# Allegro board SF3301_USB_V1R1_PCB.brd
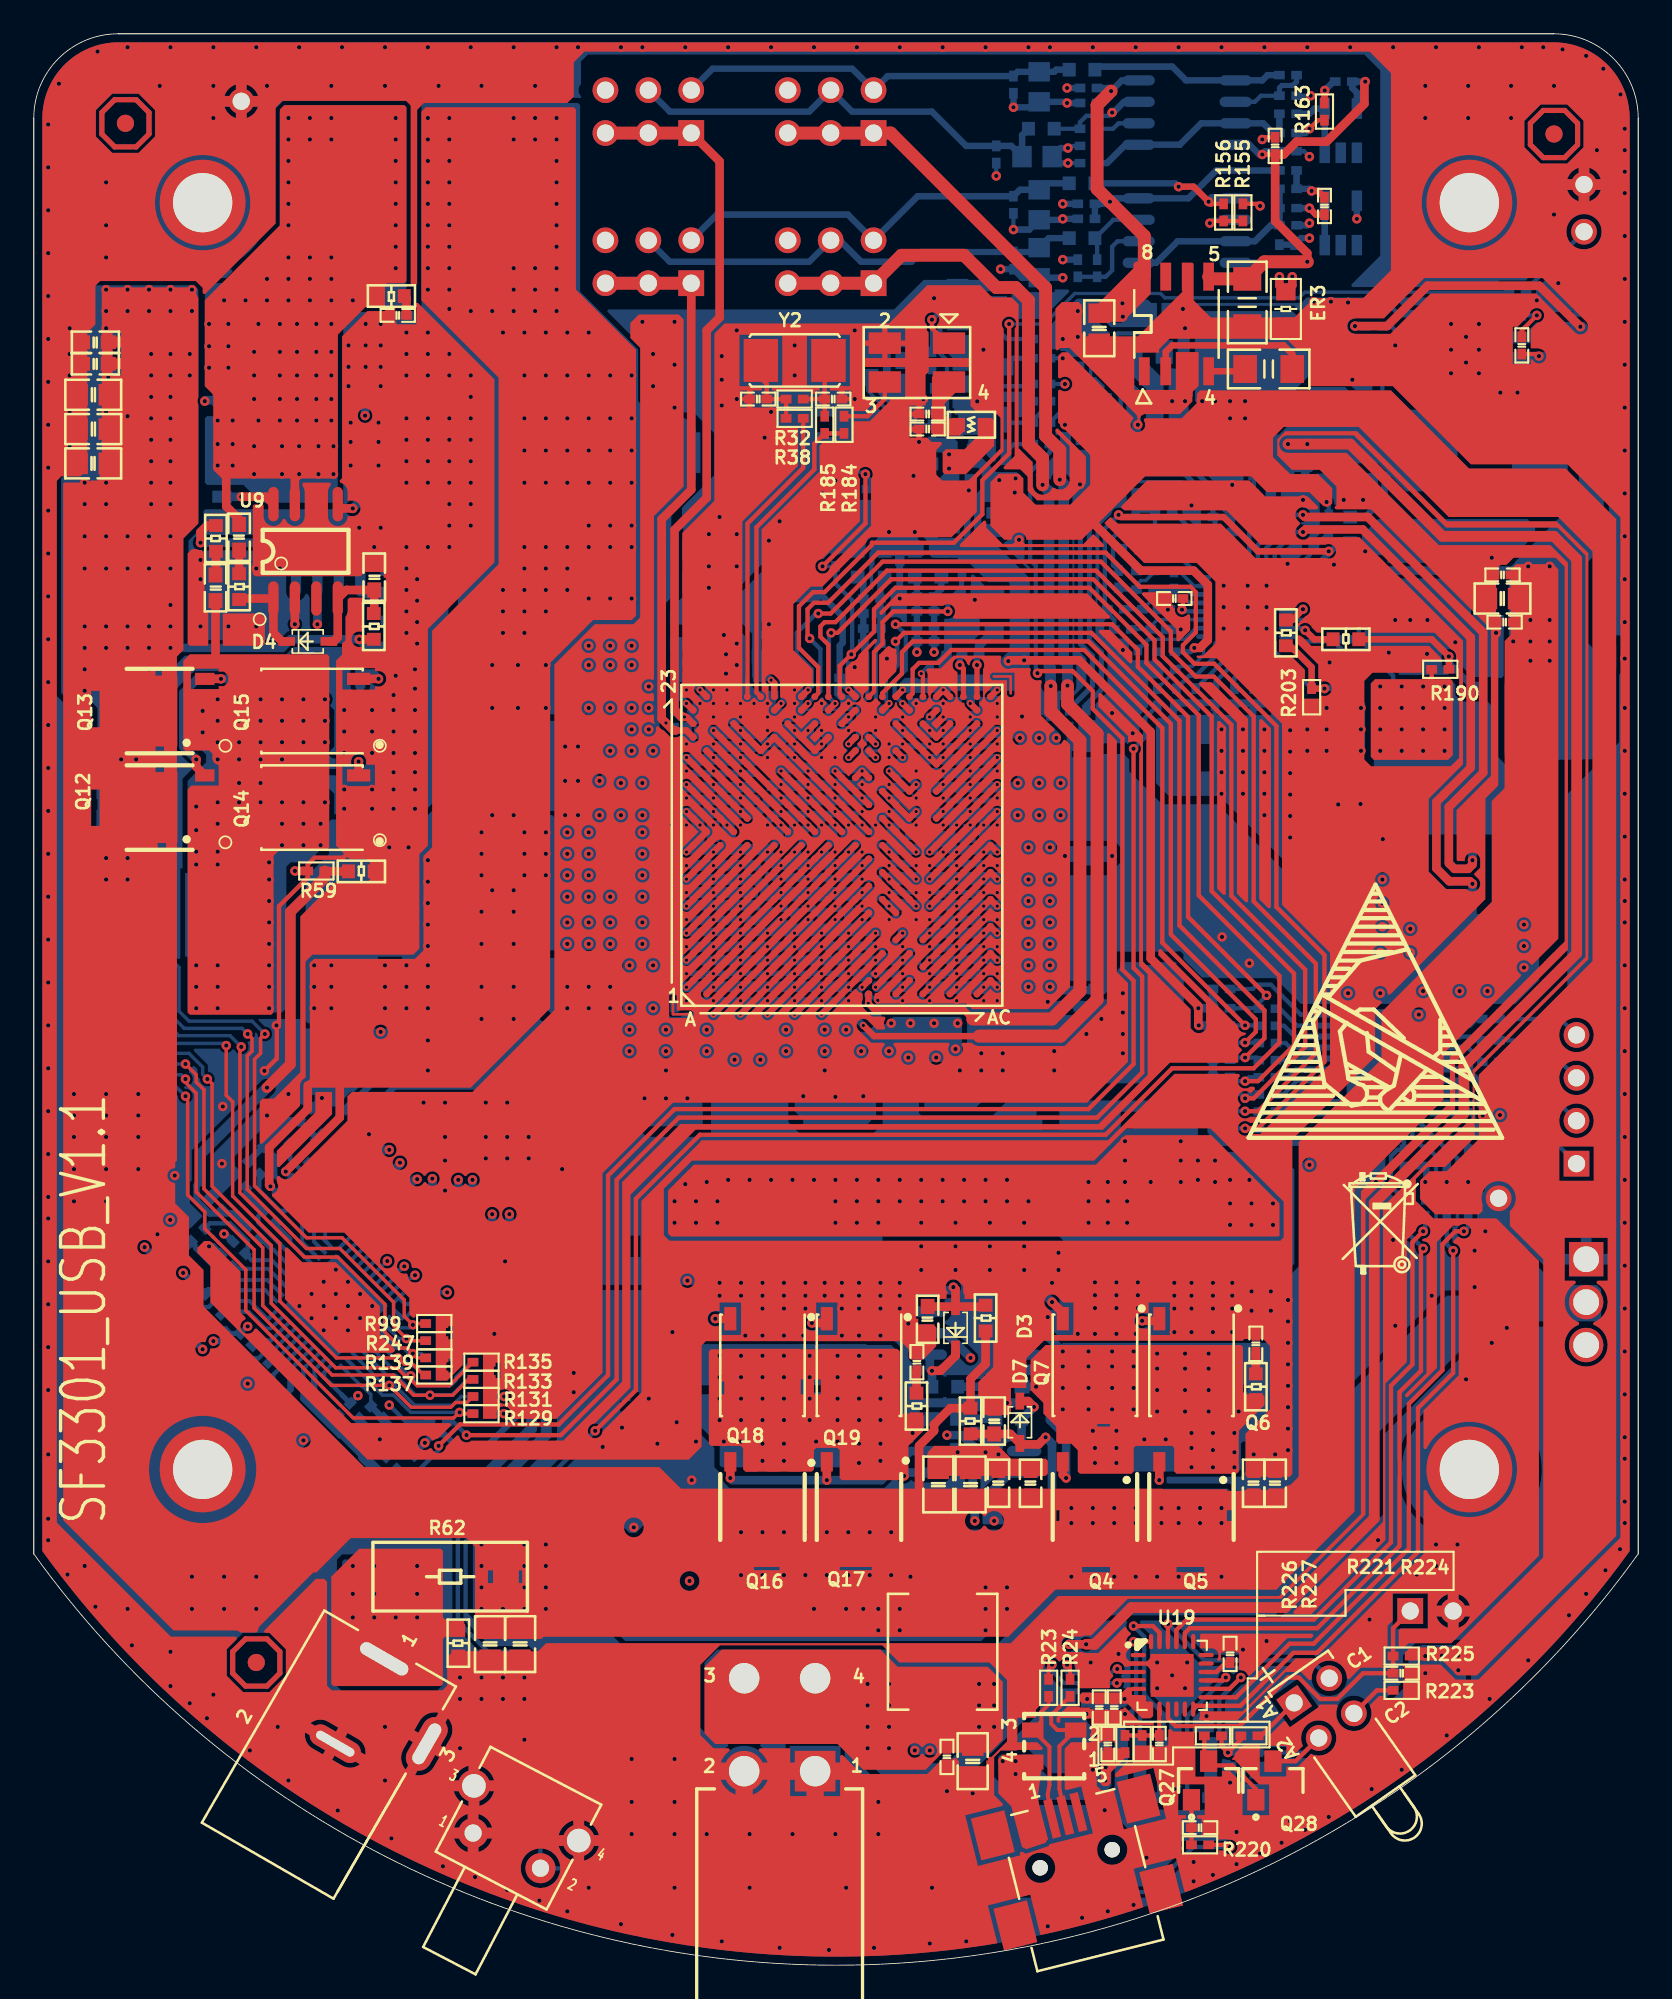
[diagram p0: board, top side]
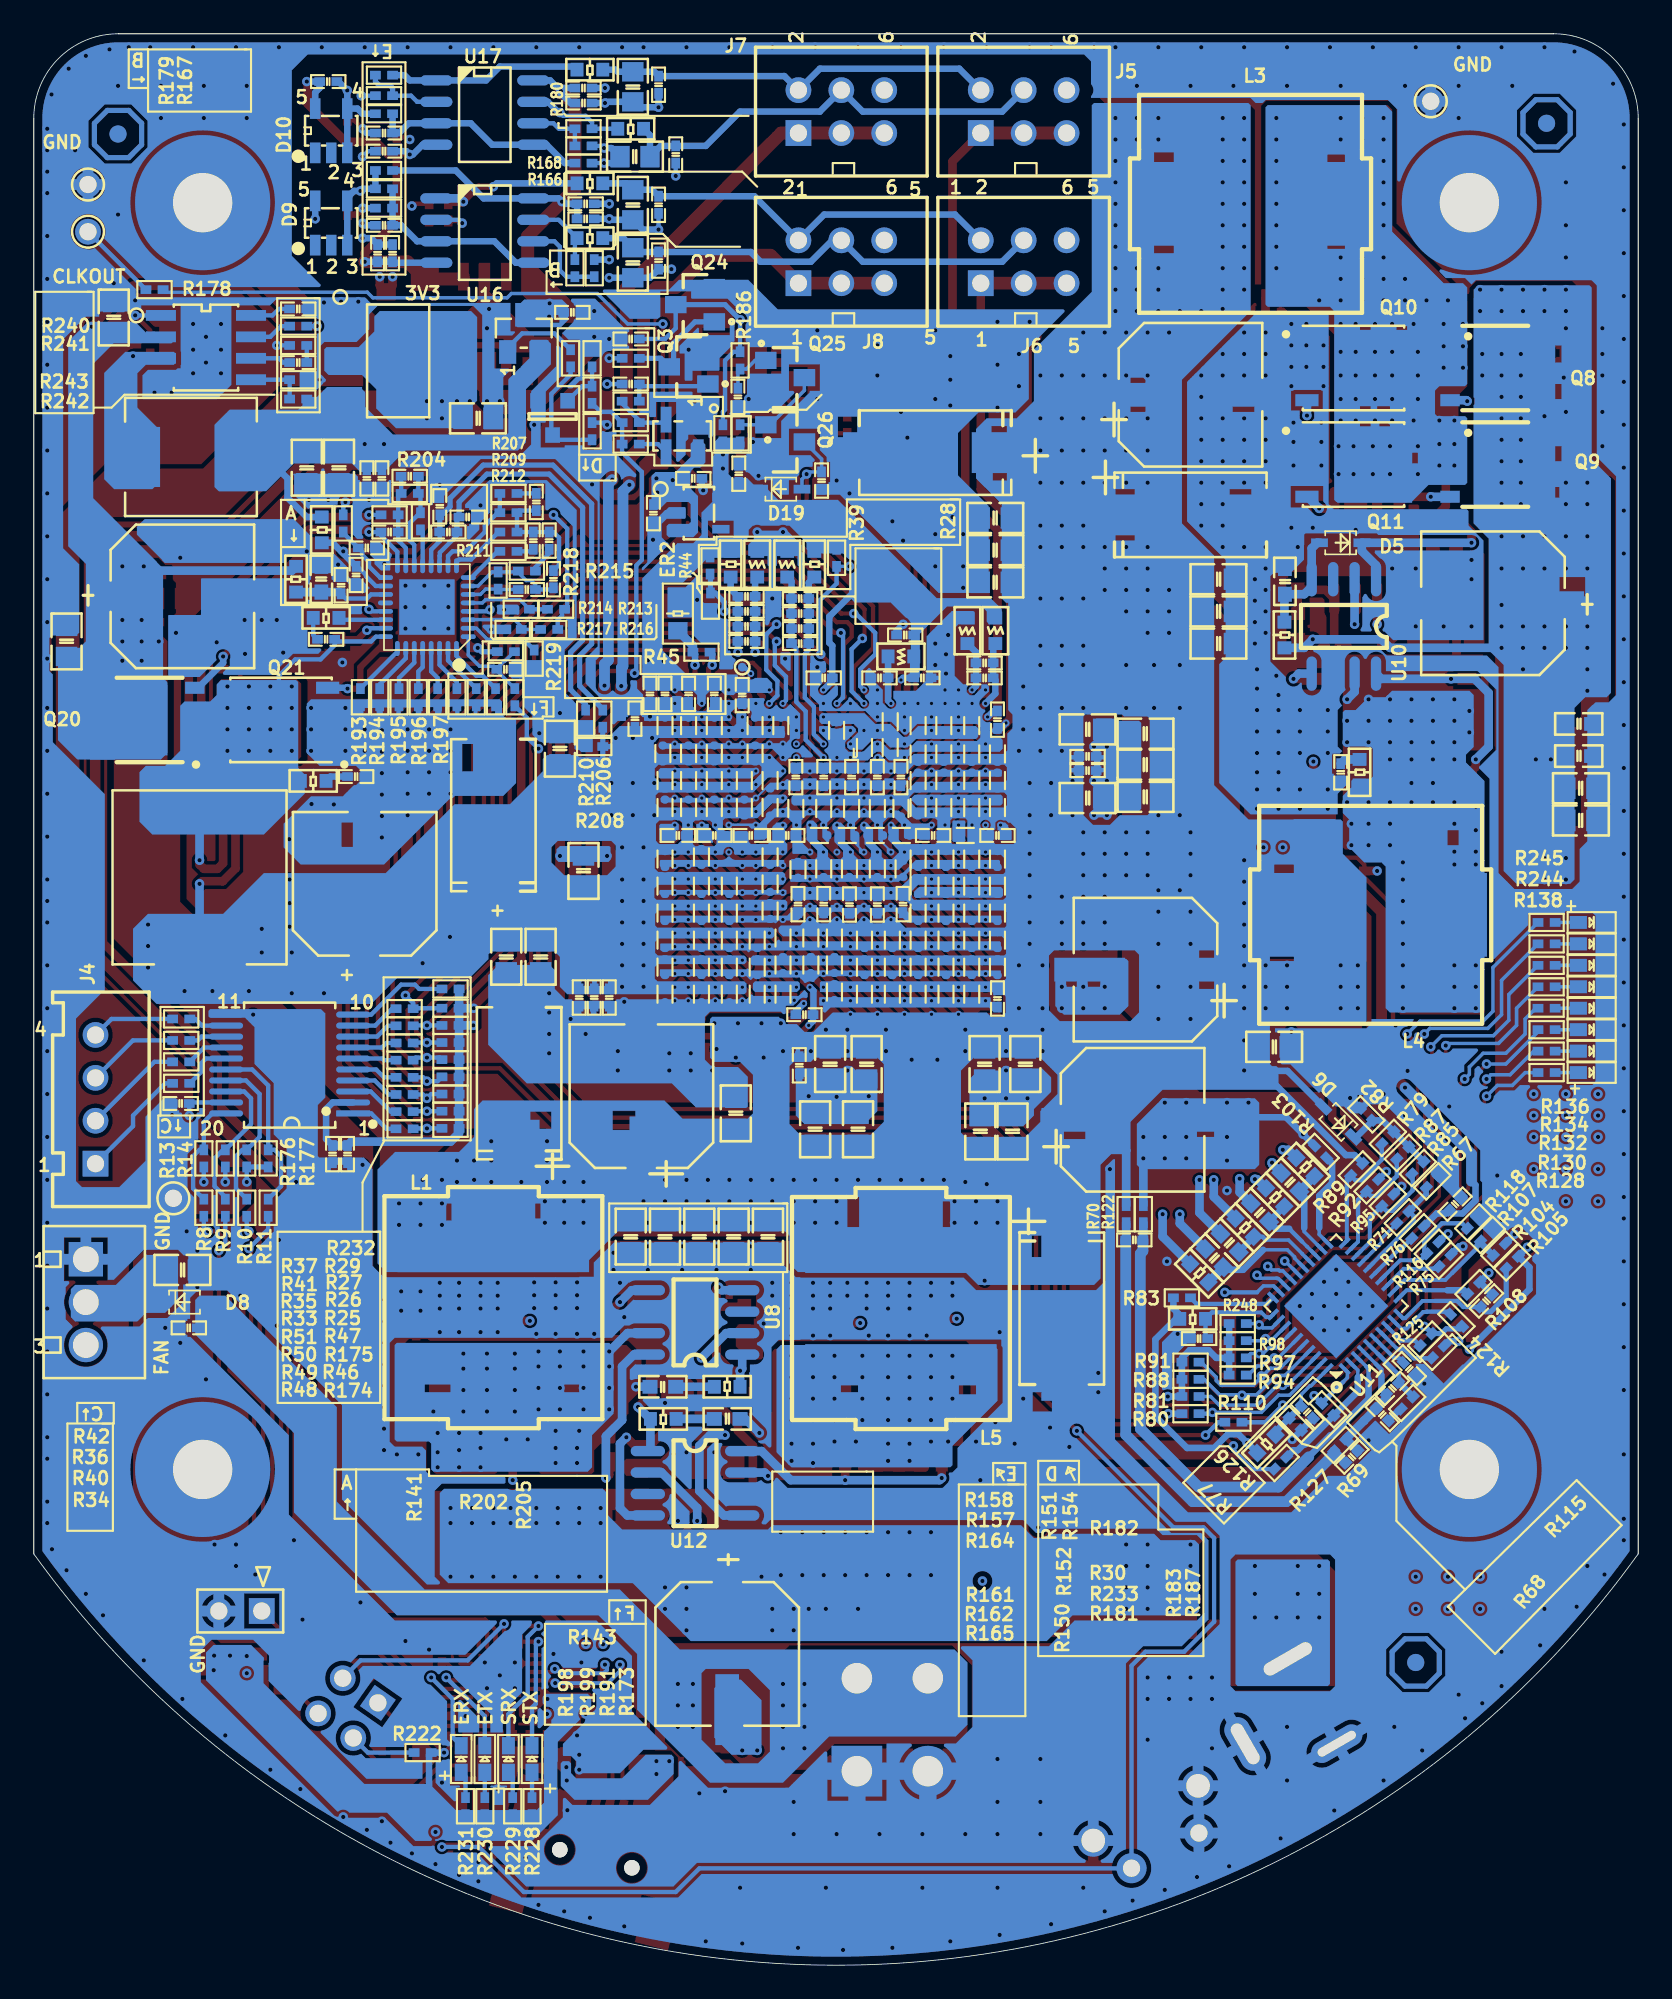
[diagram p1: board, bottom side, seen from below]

Outline 95 x 114.35 mm; copper layers: TOP, ART02, ART03, BOTTOM. Coordinates in mm from the lower left corner of the outline.
Outline path: 0,109.35 0,24.35 ; 0,109.35 arc(1.46,112.89) 5,114.35 ; 0,109.35 0,24.35 ; 0,24.35 arc(47.5,0) 95,24.35 ; 5,114.35 90,114.35 ; 5,114.35 90,114.35 ; 90,114.35 arc(93.53,112.89) 95,109.35 ; 95,109.35 95,24.35 ; 95,109.35 95,24.35

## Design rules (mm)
net group DIFF90: nets USB_DM USB_DP
net group DNRX0: nets DNRX0 N17535586
net group DNRX1: nets DNRX1 N17535592
net group DNTX0: nets DNTX0 N17535589
net group DNTX1: nets DNTX1 N17535595
net group ISP3: nets ISP3 RT8802A_PHASE3
net group ISP4: nets ISP4 RT8802A_PHASE4
net group LTC_PGD: nets LTC_PGD LTC_PGD_R
net group N16972391: nets N16972391 N16972492
net group N17253408: nets N17253408 N17254276
net group N17472254: nets N17472254 N17472271
net group N17472572: nets N17472572 N17488147
net group N17472645: nets N17472645 N17492409
net group N17535696: nets N17535696 N17535726
net group N17535699: nets N17535699 N17535729
net group N17535702: nets N17535702 N17535732
net group N17535705: nets N17535705 N17535735
net group RT8802A_PHASE1: nets N16973441 RT8802A_PHASE1
net group UART1_RX: nets UART1_RX UPTX0
net group UART1_TX: nets UART1_TX UPRX0
net group UART2_RX: nets UART2_RX UPTX1
net group UART2_TX: nets UART2_TX UPRX1
net group VCC_N0V5: nets N17032770 VCC_N0V5
net group VCC_P0V5: nets N17032029 VCC_P0V5
net group VID0: nets N16973189 VID0
net group VID1: nets N16973186 VID1
net group VID3: nets N16973195 VID3
net group VID4: nets N16973214 VID4
net group VID5: nets N16973217 VID5
net group 6314_ISEN: nets 6314_ISEN 6314_ISEN- N17472139 N17472149 N17472629 N17495070 N17497213
net group BTC_PGD: nets BTC_PGD N16975081 N17261273
net group FAN: nets 0 AVDD_THS BTC_GNDS_0 BTC_GNDS_1 BTC_VDD BTC_VDDS_0 BTC_VDDS_1 LTC_VDD N16884503 N16885409 N16885936 N16887961 N16887964 OSC_BP OSC_ZO RST_SF3301 VCC_1V8 VDDA_OSC VDDA_PLL0 VDDA_PLL1 VSSA_PLL0 VSSA_PLL1
net group ISN1: nets ISN1 ISN24 VCORE
net group N17472208: nets N17472208 N17472210 N17472223 N17472288
net group N17472302: nets N17472302 N17472317 N17489529
net group USB_DM: nets N17460832
net group USB_DP: nets N17460836
net group V6314_VCC: nets N17472408 N17472474 V6314_VCC VCC_5V0
net group VCC_1V0: nets N17031808 N17031818 VCC_1V0
net group VCC_N1V0: nets N17253373 N17253375 VCC_N1V0
net group VCC_P5V0: nets N17031806 N17031906 VCC_P5V0
net group XCLKIN: nets N16884499 N17511574 XCLKIN

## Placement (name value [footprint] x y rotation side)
C13  0.1uF  [C0402]  74.39 88.03 90 bottom
C14  10uF  [C0402]  75.28 88.03 270 bottom
C15  22uF  [C0805]  68.7 91.58 180 bottom
C18  27pF  [C0402]  47.34 92.73 0 top
C20  27pF  [C0402]  42.89 92.73 180 top
C22  0.1uF  [C0402]  86.3 51.02 180 bottom
C23  0.1uF  [C0402]  76.42 48.02 270 bottom
C24  0.1uF  [C0402]  38.7 76.22 0 bottom
C25  0.1uF  [C0402]  44.92 76.22 0 bottom
C26  4.7uF  [C0402]  58.51 75.27 270 bottom
C27  0.1uF  [C0402]  56.23 75.27 90 bottom
C28  0.1uF  [C0402]  53.05 75.2 90 bottom
C29  0.1uF  [C0402]  54.7 75.27 90 bottom
C30  0.1uF  [C0402]  57.62 75.27 90 bottom
C31  0.1uF  [C0402]  43.4 78.76 180 bottom
C32  0.1uF  [C0402]  48.22 76.22 180 bottom
C33  0.1uF  [C0402]  42.38 76.22 0 bottom
C34  2.2uF  [C0402]  49.62 78.25 0 bottom
C35  0.1uF  [C0402]  49.62 79.14 180 bottom
C36  0.01uF  [C0402]  49.62 80.03 180 bottom
C37  1000pF  [C0402]  49.62 80.91 180 bottom
C38  0.1uF  [C0402]  37.94 73.75 90 bottom
C39  0.1uF  [C0402]  49.37 56.28 180 bottom
C40  2.2uF  [C0402]  52.8 80.15 180 bottom
C41  0.1uF  [C0402]  52.8 78.37 0 bottom
C42  0.01uF  [C0402]  52.8 79.26 0 bottom
C43  1000pF  [C0402]  52.8 81.04 0 bottom
C44  4.7uF  [C0402]  58.31 85.97 270 bottom
C45  4.7uF  [C0402]  53.25 88.31 90 bottom
C46  22uF  [C0805]  38.7 53.36 270 bottom
C47  22uF  [C0805]  36.29 53.36 270 bottom
C48  22uF  [C0805]  45.68 53.36 270 bottom
C49  22uF  [C0805]  32.6 73.17 180 bottom
C50  22uF  [C0805]  47.84 53.36 270 bottom
C51  22uF  [C0805]  32.6 69.1 180 bottom
C62  10uF  [C0402]  43.53 62.82 270 bottom
C63  10uF  [C0402]  49.88 70.34 270 bottom
C64  10uF  [C0402]  48.22 70.34 270 bottom
C65  10uF  [C0402]  37.94 57.24 270 bottom
C66  10uF  [C0402]  46.57 70.34 270 bottom
C67  10uF  [C0402]  32.6 70.73 180 bottom
C68  10uF  [C0402]  49.75 62.82 270 bottom
C69  10uF  [C0402]  45.05 70.34 270 bottom
C70  10uF  [C0402]  43.65 70.34 270 bottom
C71  10uF  [C0402]  49.67 53.28 270 bottom
C72  10uF  [C0402]  46.7 62.8 270 bottom
C73  10uF  [C0402]  48.22 62.82 270 bottom
C74  10uF  [C0402]  41.75 66.89 0 bottom
C75  10uF  [C0402]  37.94 66.89 180 bottom
C76  10uF  [C0402]  32.6 71.57 180 bottom
C77  10uF  [C0402]  45.05 62.8 270 bottom
C78  2.2uF  [C0402_BGA]  37.94 63.89 270 bottom
C79  2.2uF  [C0402_BGA]  37.94 62.29 270 bottom
C80  2.2uF  [C0402_BGA]  37.94 60.69 270 bottom
C81  2.2uF  [C0402_BGA]  39.46 71.71 90 bottom
C82  2.2uF  [C0402_BGA]  41.11 70.14 90 bottom
C83  2.2uF  [C0402_BGA]  40.99 60.69 270 bottom
C84  2.2uF  [C0402_BGA]  37.94 70.14 90 bottom
C85  2.2uF  [C0402_BGA]  42.64 70.14 90 bottom
C86  2.2uF  [C0402_BGA]  44.16 59.09 270 bottom
C87  2.2uF  [C0402_BGA]  37.94 71.71 90 bottom
C88  2.2uF  [C0402_BGA]  52.16 59.09 270 bottom
C89  2.2uF  [C0402_BGA]  48.22 64.91 270 bottom
C90  2.2uF  [C0402_BGA]  37.94 59.09 270 bottom
C91  2.2uF  [C0402_BGA]  46.7 64.91 270 bottom
C92  2.2uF  [C0402_BGA]  37.94 65.49 270 bottom
C93  2.2uF  [C0402_BGA]  42.64 71.71 90 bottom
C94  2.2uF  [C0402_BGA]  49.88 68.49 270 bottom
C95  2.2uF  [C0402_BGA]  46.57 68.49 270 bottom
C96  2.2uF  [C0402_BGA]  44.29 73.62 90 bottom
C97  2.2uF  [C0402_BGA]  49.75 64.86 270 bottom
C98  2.2uF  [C0402_BGA]  40.99 65.49 270 bottom
C99  2.2uF  [C0402_BGA]  39.84 66.89 0 bottom
C100  2.2uF  [C0402_BGA]  47.46 73.11 270 bottom
C101  2.2uF  [C0402_BGA]  42.64 62.29 270 bottom
C102  2.2uF  [C0402_BGA]  45.81 72.09 270 bottom
C103  2.2uF  [C0402_BGA]  45.05 64.91 270 bottom
C104  2.2uF  [C0402_BGA]  39.46 65.49 270 bottom
C105  2.2uF  [C0402_BGA]  48.22 68.49 270 bottom
C106  2.2uF  [C0402_BGA]  43.53 64.91 270 bottom
C107  2.2uF  [C0402_BGA]  45.18 66.89 180 bottom
C108  2.2uF  [C0402_BGA]  48.99 60.82 270 bottom
C109  2.2uF  [C0402_BGA]  39.46 60.69 270 bottom
C110  2.2uF  [C0402_BGA]  42.64 60.69 270 bottom
C111  2.2uF  [C0402_BGA]  48.99 59.22 270 bottom
C112  2.2uF  [C0402_BGA]  48.48 66.89 180 bottom
C113  2.2uF  [C0402_BGA]  43.63 66.89 180 bottom
C114  2.2uF  [C0402_BGA]  39.46 59.09 270 bottom
C115  2.2uF  [C0402_BGA]  42.64 63.89 270 bottom
C116  2.2uF  [C0402_BGA]  46.83 66.89 180 bottom
C117  2.2uF  [C0402_BGA]  44.16 57.49 270 bottom
C118  2.2uF  [C0402_BGA]  52.16 57.49 270 bottom
C119  2.2uF  [C0402_BGA]  50.64 59.22 270 bottom
C120  2.2uF  [C0402_BGA]  50.64 57.49 270 bottom
C121  2.2uF  [C0402_BGA]  44.16 60.69 270 bottom
C122  2.2uF  [C0402_BGA]  45.81 59.09 270 bottom
C123  2.2uF  [C0402_BGA]  41.11 71.71 90 bottom
C124  2.2uF  [C0402_BGA]  50.64 60.82 270 bottom
C125  2.2uF  [C0402_BGA]  45.81 57.49 270 bottom
C126  2.2uF  [C0402_BGA]  41.11 73.39 90 bottom
C127  2.2uF  [C0402_BGA]  42.64 73.39 90 bottom
C128  2.2uF  [C0402_BGA]  40.99 62.29 270 bottom
C129  2.2uF  [C0402_BGA]  40.99 63.89 270 bottom
C130  2.2uF  [C0402_BGA]  41.11 68.54 90 bottom
C131  2.2uF  [C0402_BGA]  42.64 65.49 270 bottom
C132  2.2uF  [C0402_BGA]  39.46 57.49 270 bottom
C133  2.2uF  [C0402_BGA]  47.59 57.62 270 bottom
C134  2.2uF  [C0402_BGA]  47.59 60.82 270 bottom
C135  2.2uF  [C0402_BGA]  39.46 70.14 90 bottom
C136  2.2uF  [C0402_BGA]  43.65 68.49 270 bottom
C137  2.2uF  [C0402_BGA]  44.29 72.09 270 bottom
C138  2.2uF  [C0402_BGA]  39.46 68.54 90 bottom
C139  2.2uF  [C0402_BGA]  45.81 60.69 270 bottom
C140  2.2uF  [C0402_BGA]  42.64 57.49 270 bottom
C141  2.2uF  [C0402_BGA]  40.99 57.49 270 bottom
C142  2.2uF  [C0402_BGA]  39.46 63.89 270 bottom
C143  2.2uF  [C0402_BGA]  39.46 73.39 90 bottom
C144  2.2uF  [C0402_BGA]  42.64 68.54 90 bottom
C145  2.2uF  [C0402_BGA]  37.94 68.54 90 bottom
C146  2.2uF  [C0402_BGA]  45.05 68.49 270 bottom
C147  2.2uF  [C0402_BGA]  42.64 59.09 270 bottom
C148  2.2uF  [C0402_BGA]  47.59 59.22 270 bottom
C149  2.2uF  [C0402_BGA]  40.99 59.09 270 bottom
C150  2.2uF  [C0402_BGA]  39.46 62.29 270 bottom
C201  22uF  [C0805]  62.45 64.79 90 bottom
C202  22uF  [C0805]  64.99 59.71 270 bottom
C203  22uF  [C0805]  67.02 59.71 270 bottom
C204  22uF  [C0805]  63.85 72.02 90 bottom
C205  10uF  [C0402]  50.38 66.89 180 bottom
C206  10uF  [C0402]  52.54 66.89 180 bottom
C207  10uF  [C0402]  56.86 66.89 0 bottom
C208  10uF  [C0402]  54.7 66.89 0 bottom
C209  2.2uF  [C0402_BGA]  56.23 71.74 90 bottom
C210  2.2uF  [C0402_BGA]  50.76 73.39 90 bottom
C211  2.2uF  [C0402_BGA]  53.81 59.09 270 bottom
C212  2.2uF  [C0402_BGA]  53.81 57.49 270 bottom
C213  2.2uF  [C0402_BGA]  56.23 70.14 90 bottom
C214  2.2uF  [C0402_BGA]  55.46 65.62 270 bottom
C215  2.2uF  [C0402_BGA]  57.62 68.54 90 bottom
C216  2.2uF  [C0402_BGA]  54.7 70.14 90 bottom
C217  2.2uF  [C0402_BGA]  51.4 64.02 270 bottom
C218  2.2uF  [C0402_BGA]  52.29 73.39 90 bottom
C219  2.2uF  [C0402_BGA]  57.62 70.14 90 bottom
C220  2.2uF  [C0402_BGA]  51.4 68.54 270 bottom
C221  2.2uF  [C0402_BGA]  51.4 70.14 270 bottom
C222  2.2uF  [C0402_BGA]  52.92 70.14 90 bottom
C223  2.2uF  [C0402_BGA]  52.92 68.54 90 bottom
C224  2.2uF  [C0402_BGA]  54.7 73.39 90 bottom
C225  2.2uF  [C0402_BGA]  54.7 71.74 90 bottom
C226  2.2uF  [C0402_BGA]  53.81 60.69 270 bottom
C227  2.2uF  [C0402_BGA]  51.4 62.42 270 bottom
C228  2.2uF  [C0402_BGA]  54.7 68.54 90 bottom
C229  2.2uF  [C0402_BGA]  56.23 73.39 90 bottom
C230  2.2uF  [C0402_BGA]  52.29 71.74 90 bottom
C231  2.2uF  [C0402_BGA]  55.46 63.89 270 bottom
C232  2.2uF  [C0402_BGA]  56.23 68.54 90 bottom
C233  2.2uF  [C0402_BGA]  51.4 65.62 270 bottom
C234  2.2uF  [C0402_BGA]  57.62 73.39 90 bottom
C235  2.2uF  [C0402_BGA]  52.16 60.69 270 bottom
C236  2.2uF  [C0402_BGA]  53.81 63.89 270 bottom
C237  2.2uF  [C0402_BGA]  55.46 60.69 270 bottom
C238  2.2uF  [C0402_BGA]  57.62 65.49 270 bottom
C239  2.2uF  [C0402_BGA]  57.62 63.89 270 bottom
C240  2.2uF  [C0402_BGA]  57.62 62.29 270 bottom
C241  2.2uF  [C0402_BGA]  57.62 57.49 270 bottom
C242  2.2uF  [C0402_BGA]  55.46 62.29 270 bottom
C243  2.2uF  [C0402_BGA]  53.81 62.29 270 bottom
C244  2.2uF  [C0402_BGA]  57.62 60.69 270 bottom
C245  2.2uF  [C0402_BGA]  57.62 59.09 270 bottom
C246  2.2uF  [C0402_BGA]  55.46 59.09 270 bottom
C247  2.2uF  [C0402_BGA]  55.46 57.49 270 bottom
C248  2.2uF  [C0402_BGA]  57.75 71.74 90 bottom
C249  10uF/16V  [C0805]  28.79 19.01 90 top
C250  0.1uF/16V  [C0603]  72.23 28.53 270 top
C251  0.1uF/16V  [C0603]  57.75 34.25 180 bottom
C252  10uF/16V  [C0805]  27.02 19.01 90 top
C253  0.1uF/16V  [C0603]  73.5 28.53 270 top
C254  0.1uF/16V  [C0603]  52.92 38.24 270 top
C255  1000pF  [C0402]  54.07 12.33 270 top
C256  10uF/16V  [C0805]  55.59 12.08 270 top
C257  10uF/16V  [C0805]  3.52 88.92 180 top
C258  3.3nF  [C0402]  72.35 36.79 270 top
C259  0.1uF/16V  [C0603]  12.16 84.54 270 top
C260  10uF/16V  [C0805]  3.39 67.78 0 bottom
C261  0.1uF/16V  [C0603]  3.52 71.59 0 bottom
C262  10uF/16V  [C0805]  3.39 69.68 0 bottom
C263  0.1uF/16V  [C0603]  3.52 73.49 0 bottom
C264  0.1uF/16V  [C0603]  20.16 82.18 90 top
C265  68nF  [C0402]  13.55 35.32 225 bottom
C267  47pF  [C0402]  14.54 34.15 135 bottom
C268  2.2nF  [C0402]  15.16 32.6 225 bottom
C269  1.5nF  [C0402]  16.95 30.08 135 bottom
C270  3.3nF  [C0402]  21.55 97.68 0 top
C271  0.1uF  [C0402]  29.84 42.94 0 bottom
C272  10uF/16V  [C0805]  3.52 90.95 0 top
C273  0.1uF/16V  [C0603]  3.65 94.81 0 top
C274  10uF/16V  [C0805]  3.52 92.98 0 top
C275  0.1uF/16V  [C0603]  3.65 96.08 0 top
C276  270pF/NC  [C0402]  10.84 45.06 315 bottom
C277  0.1uF/16V  [C0603]  10.76 81.55 90 top
C278  0.1uF/16V  [C0603]  20.92 81.93 90 bottom
C279  0.1uF/NC  [C0402]  19.59 32.75 45 bottom
C280  1uF/16V  [C0603]  20.6 46.36 225 bottom
C281  3.3nF  [C0402]  17.62 70.63 90 bottom
C282  1uF/16V  [C0603]  22.4 44.56 225 bottom
C283  1uF/16V  [C0603]  24.19 42.77 225 bottom
C284  1uF/16V  [C0603]  25.09 41.87 225 bottom
C285  0.1uF/16V  [C0603]  59.02 28.53 270 top
C286  0.1uF/16V  [C0603]  53.94 32.34 0 bottom
C287  2.2uF  [C0402]  26 37.1 0 bottom
C288  10uF/16V  [C0805]  55.46 28.46 270 top
C289  0.1uF/16V  [C0603]  57.11 28.53 270 top
C290  10uF/16V  [C0805]  53.56 28.46 270 top
C291  0.1uF/16V  [C0603]  56.86 32.22 90 top
C292  0.1uF/NC  [C0402]  8.98 39.33 315 bottom
C294  3.3nF  [C0402]  52.29 35.7 270 top
C297  22uF  [C0805]  29.17 69.17 0 bottom
C298  22uF  [C0805]  24.86 82.06 180 bottom
C299  22uF  [C0805]  29.17 71.08 0 bottom
C300  22uF  [C0805]  57.62 43.14 270 bottom
C301  22uF  [C0805]  53.56 43.14 270 bottom
C302  22uF  [C0805]  55.59 43.14 270 bottom
C303  22uF  [C0805]  51.53 43.14 270 bottom
C304  22uF  [C0805]  21.55 54.37 180 bottom
C305  22uF  [C0805]  53.43 50.43 90 bottom
C306  22uF  [C0805]  59.65 43.14 270 bottom
C307  22uF  [C0805]  29.17 72.91 0 bottom
C308  22uF  [C0805]  24.86 78.25 180 bottom
C309  22uF  [C0805]  48.73 49.49 90 bottom
C310  22uF  [C0805]  46.19 49.49 90 bottom
C311  22uF  [C0805]  38.95 49.36 90 bottom
C312  22uF  [C0805]  37.05 49.36 90 bottom
C313  22uF  [C0805]  38.06 83.78 0 bottom
C314  22uF  [C0805]  38.06 85.68 0 bottom
C315  22uF  [C0805]  38.06 81.87 0 bottom
C316  22uF  [C0805]  24.86 80.15 180 bottom
C318  10uF/16V  [C0805]  86.96 80.91 180 top
C319  0.1uF  [C0402]  87.09 79.52 180 top
C320  10uF/16V  [C0805]  93.06 78.37 90 bottom
C321  0.01uF  [C0402]  86.96 82.31 0 top
C323  10uF  [C0402]  61.81 57.29 270 bottom
C324  10uF  [C0402]  62.7 57.29 270 bottom
C325  10uF  [C0402]  60.92 57.29 270 bottom
C326  0.1uF  [C0402]  85.82 37.73 0 bottom
C327  10uF/16V  [C0805]  86.2 41.16 180 bottom
C328  0.1uF  [C0402]  63.11 97.86 180 bottom
C329  22uF  [C0805]  63.08 96.92 270 top
C330  22uF  [C0805]  78.83 88.66 270 bottom
C331  10uF/16V  [C0805]  90.26 97.55 90 bottom
C332  100uF  [C1206]  73.12 94.5 180 top
C333  100uF  [C1206]  71.85 98.44 270 top
C334  0.1uF  [C0402]  62.32 104.28 0 bottom
C335  0.1uF  [C0402]  62.45 111.14 0 bottom
C336  22uF  [C0805]  59.53 104.23 270 bottom
C337  0.1uF  [C0402]  58 104.23 270 bottom
C338  0.1uF  [C0402]  74.26 103.01 0 bottom
C339  0.1uF  [C0402]  74.64 101.36 270 bottom
C340  0.1uF  [C0402]  74.26 108.47 0 bottom
C341  0.1uF  [C0402]  74.26 107.4 180 bottom
C342  22uF  [C0805]  59.53 111.21 270 bottom
C343  0.1uF  [C0402]  58 111.34 270 bottom
C344  4.7uF  [C0402]  76.42 104.16 270 top
C345  4.7uF  [C0402]  77.56 111.52 0 bottom
C346  22uF  [C0805]  59.53 100.8 270 bottom
C347  0.1uF  [C0402]  58 100.92 270 bottom
C348  22uF  [C0805]  59.4 107.08 0 bottom
C349  0.1uF  [C0402]  56.99 107.2 270 bottom
C350  0.1uF  [C0402]  55.95 88.03 180 bottom
C351  2.2uF  [C0402]  52.92 91.84 180 top
C352  0.1uF  [C0402]  52.92 90.95 180 top
C353  0.1uF  [C0402]  59.65 93.61 180 bottom
C354  0.1uF  [C0402]  59.65 96.28 180 bottom
C355  0.1uF  [C0402]  53.3 92.85 90 bottom
C356  0.1uF  [C0402]  48.35 87.9 90 bottom
C357  0.1uF  [C0402]  75.91 82.31 90 bottom
C358  4.7uF/16V  [C0603]  77.97 82.06 270 bottom
C359  0.1uF  [C0402]  67.07 76.72 180 bottom
C360  1uF  [C0402]  75.28 83.91 180 bottom
C361  0.1uF  [C0402]  77.69 78.5 180 bottom
C362  0.1uF  [C0402]  73.93 84.85 0 bottom
C363  1nF  [C0402]  75.91 70.37 0 bottom
C364  0.01uF  [C0402]  72.74 88.15 0 bottom
C365  0.1uF  [C0402]  59.4 73.8 270 bottom
C366  10pF/NC  [C0402]  70.96 86.38 90 bottom
C367  3.3nF  [C0402]  65.24 86.63 270 bottom
C368  10pF/NC  [C0402]  70.45 84.85 0 bottom
C369  1nF  [C0402]  65.42 84.34 90 bottom
C370  10pF/NC  [C0402]  69.31 85.74 0 bottom
C371  100pF  [C0402]  64.23 82.06 90 bottom
C372  0.01uF  [C0402]  67.53 80.91 0 top
C373  1nF  [C0402]  65.8 81.45 180 bottom
C374  6.8nF  [C0402]  64.48 84.34 90 bottom
C375  0.1uF  [C0402]  69.05 8.14 180 top
C376  4.7uF  [C0402]  63.97 15.26 90 top
C377  0.1uF  [C0402]  63.08 15.26 90 top
C378  4.7uF/NC  [C0402]  70.83 18.43 270 top
C379  0.1uF  [C0402]  80.99 17.29 180 top
C380  10uF  [C0402]  63.59 13.1 270 top
C381  2.2uF/NC  [C0402]  66.64 13.1 90 top
C382  2.2uF  [C0402]  38.7 77.1 0 bottom
C383  4.7uF  [C0402]  62.32 103.39 0 bottom
C384  4.7uF  [C0402]  73.75 101.36 270 bottom
C385  4.7uF  [C0402]  62.45 110.25 0 bottom
C386  4.7uF  [C0402]  73.5 107.71 270 top
C387  22uF  [C0805]  76.93 88.66 270 bottom
C388  0.1uF  [C0402]  88.1 95.9 270 top
C389  3.3nF  [C0402]  79.34 94.88 180 bottom
C390  0.01uF  [C0402]  79.34 98.06 0 bottom
C391  0.1uF  [C0402]  76.8 81.7 270 bottom
C392  4.7uF  [C0402]  77.31 48.02 270 bottom
CP1  270uF/16V  [CAP_D8_SMT]  53.94 18.43 270 bottom
CP2  270uF/16V  [CAP_D8_SMT]  8.6 80.64 0 bottom
CP3  1000uF/2.5V  [CAP_D8_SMT]  26.51 92.98 180 bottom
CP4  1000uF/2.5V  [CAP_D8_SMT]  59.02 51.45 90 bottom
CP5  1000uF/2.5V  [CAP_D8_SMT]  29.17 58.94 0 bottom
CP6  1000uF/2.5V  [CAP_D8_SMT]  29.94 50.05 180 bottom
CP7  1000uF/2.5V  [CAP_D8_SMT]  75.4 64.02 90 bottom
CP8  270uF/16V  [CAP_D8_SMT]  86.2 81.04 180 bottom
D1  LED ARRAY  [A694B]  77.12 14.18 125 top
D2  SP0503BAHTG  [SOT143-4]  60.42 12.97 90 top
D3  1N4148  [SOD323]  54.57 37.73 270 top
D4  1N4148  [SOD323]  16.22 78.37 180 top
D5  1N4148  [SOD323]  17.62 84.22 180 bottom
D6  1N4148  [SOD323]  17.74 49.93 225 bottom
D7  1N4148  [SOD323]  58.38 32.15 90 top
D8  1N4148  [SOD323]  86.07 39.26 0 bottom
D9  TL431CDBV  [SOT-23-5]  77.39 103.15 180 bottom
D10  TL431CDBV  [SOT-23-5]  77.39 108.61 180 bottom
D13  GREEN  [LED0603]  2.76 52.85 180 bottom
D14  GREEN  [LED0603]  2.76 54.12 180 bottom
D15  GREEN  [LED0603]  2.76 55.39 180 bottom
D16  GREEN  [LED0603]  2.76 56.66 180 bottom
D17  GREEN  [LED0603]  2.76 57.93 180 bottom
D18  GREEN  [LED0603]  2.76 59.2 180 bottom
D19  1N4148  [SOD323]  50.76 87.39 0 bottom
D20  GREEN  [LED0603]  65.5 12.21 90 bottom
D21  GREEN  [LED0603]  66.89 12.21 90 bottom
D22  GREEN  [LED0603]  68.29 12.21 90 bottom
D23  GREEN  [LED0603]  69.69 12.21 90 bottom
D24  GREEN  [LED0603]  2.76 60.47 180 bottom
D25  GREEN  [LED0603]  2.76 61.74 180 bottom
ER2  ETCH_RES  [R0805]  56.86 80.03 90 bottom
ER3  ETCH_RES  [R0805]  74.13 98.06 270 top
FB4  BEAD  [FB0603]  38.06 79.01 270 bottom
FB5  BEAD  [FB0603]  43.65 77.49 0 bottom
FB7  BEAD  [FB0603]  50.38 82.95 90 bottom
FB9  BEAD  [FB0603]  52.16 82.95 90 bottom
FB10  BEAD  [FB0603]  55.51 91.2 0 top
FB11  BEAD  [FB0603]  39.72 79.01 90 bottom
H1  HOLE  [HOLE3_5P-8MM]  85 104.35 0 top
H2  HOLE  [HOLE3_5P-8MM]  10 29.35 0 top
H3  HOLE  [HOLE3_5P-8MM]  10 104.35 0 top
H4  HOLE  [HOLE3_5P-8MM]  85 29.35 0 top
J2  HDR2/NC  [HDR2_2_54MM_DIP]  82.77 20.97 0 bottom
J3  Mini USB  [MINI_USB_B]  61.66 6.52 14.1 top
J4  HDR4/NC  [CON4P2_54MM]  91.98 53.81 90 bottom
J5  HDR6  [HDR6_2X3_2_54MM_DIP]  36.39 109.74 180 bottom
J6  HDR6  [HDR6_2X3_2_54MM_DIP]  36.39 100.85 180 bottom
J7  HDR6  [HDR6_2X3_2_54MM_DIP]  47.18 109.74 180 bottom
J8  HDR6  [HDR6_2X3_2_54MM_DIP]  47.18 100.85 180 bottom
J9  POWER CONN  [PCIE_2X2P_RA]  44.16 14.24 180 top
J10  POWER JACK  [JPD1030_H224_4F]  19.52 16.02 60 top
J11  CON3_FAN  [FAN_CONNECTOR]  91.91 39.26 90 bottom
L1  0.56uH  [IHLP5050]  67.78 38.93 270 bottom
L2  1uH  [IHLP2525]  53.81 18.56 270 top
L3  0.56uH  [IHLP5050]  22.95 104.28 180 bottom
L4  0.56uH  [IHLP5050]  15.84 62.19 180 bottom
L5  0.56uH  [IHLP5050]  43.65 38.88 270 bottom
L6  1uH  [IHLP4040]  85.18 64.4 90 bottom
L8  10uH  [SRPI_0604]  85.69 89.3 0 bottom
NOREF  -  [unnamed]  13.17 17.92 180 top
NOREF#2  -  [#2]  -95 0.02 90 top
NOREF#3  -  [unnamed]  5.43 109.05 180 top
NOREF#4  -  [#2]  79.95 53.43 0 top
NOREF#5  -  [#2]  82.26 44.03 0 top
NOREF#6  -  [unnamed]  90.01 108.42 180 top
NOREF#7  -  [unnamed]  5.43 109.05 0 bottom
NOREF#8  -  [unnamed]  90.01 108.42 0 bottom
NOREF#9  -  [unnamed]  13.17 17.92 0 bottom
Q3  BC846  [SOT23]  56.23 94.63 90 bottom
Q4  RJK0305DPB  [SON-8]  62.83 26.63 270 top
Q5  RJK0305DPB  [SON-8]  68.54 26.63 270 top
Q6  RJK0331DPB  [SON-5X6]  68.54 35.52 270 top
Q7  RJK0331DPB  [SON-5X6]  62.83 35.52 270 top
Q8  RJK0305DPB  [SON-8]  7.97 94.56 180 bottom
Q9  RJK0305DPB  [SON-8]  7.97 88.85 180 bottom
Q10  RJK0331DPB  [SON-5X6]  16.86 94.56 180 bottom
Q11  RJK0331DPB  [SON-5X6]  16.86 88.85 180 bottom
Q12  RJK0305DPB  [SON-8]  6.95 68.54 180 top
Q13  RJK0305DPB  [SON-8]  6.95 74.25 180 top
Q14  RJK0331DPB  [SON-5X6]  16.47 68.54 180 top
Q15  RJK0331DPB  [SON-5X6]  16.47 74.25 180 top
Q16  RJK0305DPB  [SON-8]  43.14 26.63 270 top
Q17  RJK0305DPB  [SON-8]  48.86 26.63 270 top
Q18  RJK0331DPB  [SON-5X6]  43.14 35.52 270 top
Q19  RJK0331DPB  [SON-5X6]  48.86 35.52 270 top
Q20  RJK0305DPB  [SON-8]  88.64 73.73 0 bottom
Q21  RJK0331DPB  [SON-5X6]  80.36 73.73 0 bottom
Q22  IRLML6401  [SOT-23_PMOS]  65.99 96.61 180 bottom
Q23  2N7002  [SOT23DGS]  64.28 91.61 270 bottom
Q24  BC846  [SOT23]  55.84 98.31 90 bottom
Q25  BC846  [SOT23]  50.51 94 270 bottom
Q26  BC846  [SOT23]  50.51 90.19 270 bottom
Q27  BC846  [SOT23]  69.56 10.94 0 top
Q28  BC846  [SOT23]  73.37 10.94 0 top
R8  0  [R0402]  84.93 44.85 270 bottom
R9  0  [R0402]  83.66 44.85 270 bottom
R10  0  [R0402]  82.39 44.85 270 bottom
R11  0  [R0402]  81.12 44.85 270 bottom
R13  100K  [R0402]  84.93 47.77 270 bottom
R14  100K  [R0402]  83.66 47.77 270 bottom
R23  0  [R0402]  60.09 16.42 270 top
R24  0  [R0402]  61.36 16.42 270 top
R25  100K  [R0402]  70.32 53.61 0 bottom
R26  100K  [R0402]  70.32 54.63 0 bottom
R27  100K  [R0402]  70.32 55.64 0 bottom
R28  51K  [R0402]  47.46 83.33 270 bottom
R29  100K  [R0402]  70.32 56.66 0 bottom
R30  4.7K  [R0402]  59.65 92.6 0 bottom
R32  1M  [R0402]  45.05 92.73 180 top
R33  0  [R0402]  73.04 53.58 0 bottom
R34  0  [R0402]  86.27 52.21 0 bottom
R35  0  [R0402]  73.04 54.6 0 bottom
R36  0  [R0402]  86.27 54.75 0 bottom
R37  0  [R0402]  73.04 56.63 0 bottom
R38  33  [R0402]  45.05 91.58 0 top
R39  4.7K  [R0402]  54.96 82.87 90 bottom
R40  0  [R0402]  86.27 53.48 0 bottom
R41  0  [R0402]  73.04 55.62 0 bottom
R42  0  [R0402]  86.27 56.02 0 bottom
R44  4.7K/NC  [R0402]  54.93 80.74 270 bottom
R45  10K  [R0402]  55.46 77.74 180 bottom
R46  100K/NC  [R0402]  70.32 50.56 0 bottom
R47  100K/NC  [R0402]  70.32 52.59 0 bottom
R48  0  [R0402]  73.04 49.52 0 bottom
R49  0  [R0402]  73.04 50.54 0 bottom
R50  0  [R0402]  73.04 51.55 0 bottom
R51  0  [R0402]  73.04 52.57 0 bottom
R57  2.2R  [R0603]  56.35 38.31 270 top
R58  0R  [R0603]  53.94 34.25 180 bottom
R59  470  [R0402]  16.73 64.79 180 top
R60  10K/NTC  [R0603]  19.4 64.76 0 top
R61  2.2R  [R0603]  72.35 34.25 270 top
R62  NC  [R2512]  24.65 23 0 top
R63  10K/NC  [R0603]  25.14 19.07 90 top
R64  2.2R  [R0603]  20.13 79.26 270 top
R65  0R  [R0603]  12.16 81.62 270 top
R66  2.2R  [R0603]  21.17 98.82 180 top
R67  3.3K  [R0402]  12.19 46.41 135 bottom
R68  15K  [R0402]  13.68 33.29 135 bottom
R69  1.5K  [R0402]  17.67 30.8 135 bottom
R70  33  [R0402]  30.32 44.47 270 bottom
R71  4.7K  [R0402]  13.93 44.28 135 bottom
R72  0R  [R0603]  10.79 84.47 90 top
R73  2.2R  [R0603]  20.95 78.76 270 bottom
R75  20K  [R0402]  11.44 41.72 135 bottom
R76  180  [R0402]  13.05 43.39 135 bottom
R77  1.1K/NC  [R0402]  20.31 32.03 225 bottom
R78  2.2R  [R0603]  16.5 70.63 270 bottom
R79  100K  [R0402]  14.82 48.98 315 bottom
R80  1K  [R0402]  26.51 32.65 0 bottom
R81  1K/NC  [R0402]  26.51 33.67 0 bottom
R82  100  [R0402]  16.09 50.38 225 bottom
R83  0  [R0402]  27.02 39.51 180 bottom
R84  2.2R  [R0603]  22.02 30.87 315 bottom
R85  100K  [R0402]  13.05 47.2 315 bottom
R86  510R  [R0603]  19.7 47.26 225 bottom
R87  100K  [R0402]  13.93 48.09 315 bottom
R88  1K  [R0402]  26.51 34.69 0 bottom
R89  470  [R0402]  16.66 47.11 315 bottom
R90  510R  [R0603]  21.5 45.46 225 bottom
R91  1K/NC  [R0402]  26.51 35.7 0 bottom
R92  470  [R0402]  15.73 46.18 315 bottom
R93  510R  [R0603]  23.29 43.66 225 bottom
R94  1K/NC  [R0402]  23.71 34.94 0 bottom
R95  470  [R0402]  14.82 45.3 315 bottom
R96  510R  [R0603]  25.99 40.97 225 bottom
R97  1K  [R0402]  23.71 35.96 0 bottom
R98  1K/NC  [R0402]  23.71 36.97 0 bottom
R99  0/NC  [R0402]  23.71 37.99 180 top
R100  0R  [R0603]  57.72 32.34 0 bottom
R101  2.2R  [R0603]  55.46 32.22 90 top
R102  2.2R  [R0603]  26.38 38.27 0 bottom
R103  0  [R0402]  18.8 48.15 225 bottom
R104  9.1K  [R0402]  8.22 42.38 135 bottom
R105  2.2K  [R0402]  7.46 41.61 315 bottom
R107  1.1K  [R0402]  8.97 43.23 135 bottom
R108  9.1K  [R0402]  9.74 40.09 315 bottom
R109  2.2R  [R0603]  52.26 33.11 270 top
R110  0  [R0402]  23.97 32.15 0 bottom
R115  10K  [R0402]  11.84 36.32 315 bottom
R116  0/NC  [R0402]  12.16 42.48 315 bottom
R118  43K  [R0402]  9.77 43.98 315 bottom
R122  33  [R0402]  29.3 44.47 270 bottom
R124  10K  [R0402]  10.76 38.19 225 bottom
R125  10K  [R0402]  12.56 37.04 135 bottom
R126  10K  [R0402]  18.38 32.91 45 bottom
R127  0  [R0402]  21.17 29.73 315 bottom
R128  0  [R0402]  5.43 52.85 180 bottom
R129  0/NC  [R0402]  26.51 32.65 180 top
R130  0  [R0402]  5.43 54.12 180 bottom
R131  0  [R0402]  26.51 33.67 180 top
R132  0  [R0402]  5.43 55.39 180 bottom
R133  0  [R0402]  26.51 34.69 180 top
R134  0  [R0402]  5.43 56.66 180 bottom
R135  0/NC  [R0402]  26.51 35.7 180 top
R136  0  [R0402]  5.43 57.93 180 bottom
R137  0  [R0402]  23.71 34.94 180 top
R138  0  [R0402]  5.43 59.2 180 bottom
R139  0/NC  [R0402]  23.71 35.96 180 top
R140  2.2R  [R0603]  77.94 84.98 270 bottom
R141  100K  [R0402]  76.67 85.36 270 bottom
R143  100K  [R0402]  67.05 77.76 180 bottom
R150  10K  [R0402]  61.94 90.82 90 bottom
R151  0  [R0402]  63.21 95.14 270 bottom
R152  0  [R0402]  61.94 92.98 270 bottom
R154  10K/NC  [R0402]  61.94 95.14 90 bottom
R155  1K  [R0402]  71.59 103.77 90 top
R156  3.74K  [R0402]  70.45 103.77 270 top
R157  1K  [R0402]  74.26 110.68 0 bottom
R158  3.74K  [R0402]  74.26 111.9 0 bottom
R159  4.7R  [R0603]  62.07 105.5 0 bottom
R160  4.7R  [R0603]  62.07 112.23 0 bottom
R161  220  [R0402]  74.26 106.26 180 bottom
R162  1K  [R0402]  74.26 105.17 0 bottom
R163  220  [R0402]  76.42 109.74 270 top
R164  1K  [R0402]  74.26 109.62 0 bottom
R165  100  [R0402]  74.26 104.03 0 bottom
R166  100  [R0402]  62.45 106.7 180 bottom
R167  1K  [R0402]  61.81 100.47 90 bottom
R168  1K  [R0402]  62.45 107.71 180 bottom
R169  4.7R  [R0603]  62.07 102.25 0 bottom
R170  4.7R  [R0603]  59.65 108.73 0 bottom
R173  0  [R0402]  66.51 75.07 90 bottom
R174  100K/NC  [R0402]  70.32 49.55 0 bottom
R175  100K/NC  [R0402]  70.32 51.58 0 bottom
R176  100K  [R0402]  82.39 47.77 270 bottom
R177  100K  [R0402]  81.12 47.77 270 bottom
R178  0  [R0402]  87.85 99.2 180 bottom
R179  1K  [R0402]  62.96 100.47 270 bottom
R180  1K  [R0402]  62.45 108.73 0 bottom
R181  0/NC  [R0402]  59.65 90.06 0 bottom
R182  4.7K  [R0402]  59.65 95.14 0 bottom
R183  1K  [R0402]  54.19 90.69 270 bottom
R184  33  [R0402]  47.97 91.2 90 top
R185  0/NC  [R0402]  46.83 91.2 270 top
R186  1K  [R0402]  53.18 95.01 90 bottom
R187  1K  [R0402]  53.18 90.69 270 bottom
R188  2.2R  [R0603]  79.47 82.06 90 bottom
R189  2.2R  [R0603]  77.69 78.5 0 top
R190  10K  [R0402]  83.28 76.72 0 top
R191  1K  [R0402]  67.66 75.07 90 bottom
R192  2.2R  [R0603]  77.69 79.77 0 bottom
R193  1K/NC  [R0402]  75.66 75.07 90 bottom
R194  1K/NC  [R0402]  74.51 75.07 90 bottom
R195  1K/NC  [R0402]  73.37 75.07 90 bottom
R196  1K  [R0402]  72.23 75.07 90 bottom
R197  1K  [R0402]  71.08 75.07 90 bottom
R198  1K/NC  [R0402]  69.94 75.07 90 bottom
R199  1K  [R0402]  68.8 75.07 90 bottom
R200  2.2R  [R0603]  74.13 78.88 270 top
R201  2.2R  [R0603]  78.45 70.12 0 bottom
R202  8.06K  [R0402]  73.93 85.87 180 bottom
R203  10K  [R0402]  75.66 75.07 90 top
R204  75K  [R0402]  72.74 87.14 0 bottom
R205  3.24K  [R0402]  72.1 85.49 90 bottom
R206  0  [R0402]  61.31 73.8 90 bottom
R207  33  [R0402]  66.89 87.14 180 bottom
R208  33  [R0402]  61.81 72.15 180 bottom
R209  1.21K  [R0402]  66.89 85.99 180 bottom
R210  0  [R0402]  62.32 73.8 90 bottom
R211  4.99K  [R0402]  66.89 83.71 180 bottom
R212  0  [R0402]  66.89 84.85 180 bottom
R213  100K/NC  [R0402]  64.07 80.28 0 bottom
R214  5.9K/NC  [R0402]  66.16 80.28 180 bottom
R215  15.8K  [R0402]  65.8 82.54 180 bottom
R216  91K  [R0402]  64.48 79.09 0 bottom
R217  91K/NC  [R0402]  66.64 79.09 180 bottom
R218  5.11K  [R0402]  67.5 81.98 90 bottom
R219  120K  [R0402]  65.37 77.36 90 bottom
R220  1K  [R0402]  69.05 7.13 0 top
R221  1K  [R0402]  69.81 13.58 0 top
R222  1K  [R0402]  71.97 12.59 180 bottom
R223  1K  [R0402]  80.99 16.27 180 top
R224  1K  [R0402]  71.97 13.58 180 top
R225  4.7K  [R0402]  80.99 18.3 0 top
R226  24K  [R0402]  64.61 13.1 270 top
R227  47K  [R0402]  65.62 13.1 270 top
R228  1K  [R0402]  65.5 9.41 90 bottom
R229  1K  [R0402]  66.64 9.41 90 bottom
R230  1K  [R0402]  68.29 9.41 90 bottom
R231  1K  [R0402]  69.43 9.41 90 bottom
R232  1K  [R0402]  70.32 57.8 0 bottom
R233  0  [R0402]  59.65 91.33 0 bottom
R234  10R  [R0603]  48.78 82.95 270 bottom
R235  10R  [R0603]  53.74 82.95 270 bottom
R240  100K  [R0402]  79.34 97.04 180 bottom
R241  6.8K  [R0402]  79.34 95.9 0 bottom
R242  100K  [R0402]  79.34 92.73 0 bottom
R243  22K  [R0402]  79.34 93.87 180 bottom
R244  0  [R0402]  5.43 60.47 180 bottom
R245  0  [R0402]  5.43 61.74 180 bottom
R247  0  [R0402]  23.71 36.97 180 top
R248  1K/NC  [R0402]  23.71 37.99 0 bottom
SW1  Button  [TS039]  29.05 8.78 332.4 top
TC2  470uF/2.5V  [TC7343]  66.26 52.21 90 bottom
TC3  470uF/2.5V  [TC7343]  34.13 38.88 270 bottom
TC4  470uF/2.5V  [TC7343]  26.51 85.87 180 bottom
TC5  470uF/2.5V  [TC7343]  41.62 89.55 0 bottom
TC6  470uF/2.5V  [TC7343]  67.78 68.09 90 bottom
TP3  TPAD_020  [DIP]  12.28 110.35 90 bottom
TP4  TPAD_020  [DIP]  86.73 45.41 180 bottom
TP8  TPAD_020  [DIP]  91.79 102.63 180 bottom
TP9  TPAD_020  [DIP]  91.79 105.43 180 bottom
TP10  -  [TPAD_020]  53.05 76.85 180 bottom
U3  AMS1117-3.3V  [SOT-223]  73.42 94.99 270 bottom
U5  SF3301  [481FCBGA_19X19_0M8]  47.84 66.3 0 top
U6  TXS0108EPWR  [TSSOP20]  79.85 53.36 0 bottom
U7  AP7365-18WG-7  [AP7365_SOT25]  55.62 85.97 270 bottom
U8  RT9612  [SO-8]  55.84 38.06 0 bottom
U9  RT9612  [SO-8]  16.09 83.71 90 top
U10  RT9612  [SO-8]  17.43 79.26 270 bottom
U11  RT8802A  [QFN40]  17.88 39.03 45 bottom
U12  RT9612  [SO-8]  55.84 28.53 180 bottom
U13  ISL6314CR  [QFN32_5X5_R5]  71.72 80.41 0 bottom
U14  LM2662MX/NOPB  [SOIC8_TI]  67.66 97.17 0 top
U16  AD826AR  [SOP8]  68.29 102.7 180 bottom
U17  AD826AR  [SOP8]  68.29 109.69 180 bottom
U18  CAT811TTBI-GT3  [SOT143-25X60]  56.61 90.54 90 bottom
U19  CP2105-F01-GM  [QFN24-0-5]  67.4 17.16 0 top
U20  G5795F11U  [G5795F11U_SOP8FD]  84.8 95.77 270 bottom
X1  25MHz/OSC  [OSC5032]  52.29 94.88 180 top
Y2  25MHz/CRY  [CRY2P_5032]  45.05 95.01 0 top

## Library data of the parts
C13-C15 C22-C25 C38 C39 C380 C382 C392 = CAP NP
C18 C20 C27-C33 C35-C37 C41-C43 C351-C356 C375 = CAPC,X7R,0603,16V, 10%,0_0.1uF
C26 C45 C323 C324 = CAPC,X5R,0603,6.3V,20%,10uF: tolerance: 20%
C34 C40 = CAPC,X5R,0603,6.3V,20%,10uF
C44 C46-C51 C62-C150 C201-C265 C267-C292 C294 C297-C316 C318 C320 C325 C327 C331 C376-C379 C381 C383-C386 = CAP NP_5
C319 C326 = C_0
C321 = CAP
C328 C334-C350 C357-C374 C388-C391 = CAP-NP0603_0
C329 C330 C332 C333 C387 = CAPC,X5R,0805,6.3V,20%,22UF: tolerance: 20%
CP1-CP8 = CP_0
D1 = A694B_4
D2 = SP0503BAHTG
D3-D8 D19 = DIODE_0
D9 D10 = G9141P11U_3
D13-D18 D20-D25 = DLED
ER2 ER3 = ETCH_RESISTOR,0805_0
FB4 FB5 FB7 FB9-FB11 = FER,0603,60Ohm_100MHz,25%,3A
H1-H4 = MillMax-2501-2_0
J2 = CONN6,SPEAKER,E80366-001_4
J3 = Mini USB CONN
J4 = CONN6,SPEAKER,E80366-001_5
J5-J8 = CONN6,SPEAKER,E80366-001_7
J9 = CONN6,SPEAKER,E80366-001_9
J10 = DC POWER JACK
J11 = 3707K-S06N-21R_0
L1-L6 L8 = FERRITE_BEAD
Q3 Q24-Q28 = NPN_0
Q4 Q5 Q8 Q9 Q12 Q13 Q16 Q17 Q20 = 2N7000_0
Q6 Q7 Q10 Q11 Q14 Q15 Q18 Q19 Q21 = SI4410
Q22 = MOSFET_P
Q23 = 2N7002
R8-R11 R13 R25-R30 R32 R44-R46 R57-R60 R66-R73 R75 R76 R78-R84 R92-R100 R102 R105 R109 R110 R115 R116 R122 R124-R126 R132 R133 R151 R174-R183 R186 R187 R220-R235 R240-R245 R247 R248 = R_0
R14 R39 R47 R61-R65 R77 R85-R91 R101 R103 R104 R107 R108 R118 R127-R131 R134-R139 R150 R152 R154-R170 = R_0: signal model: R0603_43.2_1%
R23 R24 R33-R37 R40-R42 R48-R51 = R_0: signal model: R_0_R0402_22_22
R38 R140 R141 R143 R173 R184 R185 R188-R219 = RES: signal model: DEFAULT_RESISTOR_68000OHM_2_1; room: JTAG
SW1 = SW,HOTKEY,SKQGADE010_2: room: SLEEP_CTRL
TC2-TC6 = CAPS,AL-P,V,2.0V,20%,470uF: tolerance: 20%
TP3 TP4 TP8-TP10 = TESTLOOP
U3 = LT1117_0
U5 = SF3301_8
U6 = NLSX3378_3
U7 = G9141P11U_1
U8-U10 U12 = RT9612
U11 = RT8802A_0
U13 = HIP6301_10
U14 = LTC660CS8_0
U16 U17 = AD8072/SO_0
U18 = STM6315RDW13F_0
U19 = CP2105-F01-GM_2
U20 = G5795F11U_0
X1 = OSC-6_0
Y2 = XTAL_0

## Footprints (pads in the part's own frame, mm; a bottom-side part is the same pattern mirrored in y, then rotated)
481FCBGA_19X19_0M8
  round 0.406 smd: A1(-8.8,-8.8) A2(-8.8,-8) A3(-8.8,-7.2) A4(-8.8,-6.4) A5(-8.8,-5.6) A6(-8.8,-4.8) A7(-8.8,-4) A8(-8.8,-3.2) A9(-8.8,-2.4) A10(-8.8,-1.6) A11(-8.8,-0.8) A12(-8.8,0) A13(-8.8,0.8) A14(-8.8,1.6) A15(-8.8,2.4) A16(-8.8,3.2) A17(-8.8,4) A18(-8.8,4.8) A19(-8.8,5.6) A20(-8.8,6.4) A21(-8.8,7.2) A22(-8.8,8) A23(-8.8,8.8) AA1(7.2,-8.8) AA2(7.2,-8) AA3(7.2,-7.2) AA4(7.2,-6.4) AA5(7.2,-5.6) AA6(7.2,-4.8) AA7(7.2,-4) AA8(7.2,-3.2) AA9(7.2,-2.4) AA10(7.2,-1.6) AA11(7.2,-0.8) AA12(7.2,0) AA13(7.2,0.8) AA14(7.2,1.6) AA15(7.2,2.4) AA16(7.2,3.2) AA17(7.2,4) AA18(7.2,4.8) AA19(7.2,5.6) AA20(7.2,6.4) AA21(7.2,7.2) AA22(7.2,8) AA23(7.2,8.8) AB1(8,-8.8) AB2(8,-8) AB3(8,-7.2) AB4(8,-6.4) AB5(8,-5.6) AB6(8,-4.8) AB7(8,-4) AB8(8,-3.2) AB9(8,-2.4) AB10(8,-1.6) AB11(8,-0.8) AB12(8,0) AB13(8,0.8) AB14(8,1.6) AB15(8,2.4) AB16(8,3.2) AB17(8,4) AB18(8,4.8) AB19(8,5.6) AB20(8,6.4) AB21(8,7.2) AB22(8,8) AB23(8,8.8) AC1(8.8,-8.8) AC2(8.8,-8) AC3(8.8,-7.2) AC4(8.8,-6.4) AC5(8.8,-5.6) AC6(8.8,-4.8) AC7(8.8,-4) AC8(8.8,-3.2) AC9(8.8,-2.4) AC10(8.8,-1.6) AC11(8.8,-0.8) AC12(8.8,0) AC13(8.8,0.8) AC14(8.8,1.6) AC15(8.8,2.4) AC16(8.8,3.2) AC17(8.8,4) AC18(8.8,4.8) AC19(8.8,5.6) AC20(8.8,6.4) AC21(8.8,7.2) AC22(8.8,8) AC23(8.8,8.8) B1(-8,-8.8) B2(-8,-8) B3(-8,-7.2) B4(-8,-6.4) B5(-8,-5.6) B6(-8,-4.8) B7(-8,-4) B8(-8,-3.2) B9(-8,-2.4) B10(-8,-1.6) B11(-8,-0.8) B12(-8,0) B13(-8,0.8) B14(-8,1.6) B15(-8,2.4) B16(-8,3.2) B17(-8,4) B18(-8,4.8) B19(-8,5.6) B20(-8,6.4) B21(-8,7.2) B22(-8,8) B23(-8,8.8) C1(-7.2,-8.8) C2(-7.2,-8) C3(-7.2,-7.2) C4(-7.2,-6.4) C5(-7.2,-5.6) C6(-7.2,-4.8) C7(-7.2,-4) C8(-7.2,-3.2) C9(-7.2,-2.4) C10(-7.2,-1.6) C11(-7.2,-0.8) C12(-7.2,0) C13(-7.2,0.8) C14(-7.2,1.6) C15(-7.2,2.4) C16(-7.2,3.2) C17(-7.2,4) C18(-7.2,4.8) C19(-7.2,5.6) C20(-7.2,6.4) C21(-7.2,7.2) C22(-7.2,8) C23(-7.2,8.8) D1(-6.4,-8.8) D2(-6.4,-8) D3(-6.4,-7.2) D4(-6.4,-6.4) D5(-6.4,-5.6) D6(-6.4,-4.8) D7(-6.4,-4) D8(-6.4,-3.2) D9(-6.4,-2.4) D10(-6.4,-1.6) D11(-6.4,-0.8) D12(-6.4,0) D13(-6.4,0.8) D14(-6.4,1.6) D15(-6.4,2.4) D16(-6.4,3.2) D17(-6.4,4) D18(-6.4,4.8) D19(-6.4,5.6) D20(-6.4,6.4) D21(-6.4,7.2) D22(-6.4,8) D23(-6.4,8.8) E1(-5.6,-8.8) E2(-5.6,-8) E3(-5.6,-7.2) E4(-5.6,-6.4) E5(-5.6,-5.6) E6(-5.6,-4.8) E7(-5.6,-4) E8(-5.6,-3.2) E9(-5.6,-2.4) E10(-5.6,-1.6) E11(-5.6,-0.8) E12(-5.6,0) E13(-5.6,0.8) E14(-5.6,1.6) E15(-5.6,2.4) E16(-5.6,3.2) E17(-5.6,4) E18(-5.6,4.8) E19(-5.6,5.6) E20(-5.6,6.4) E21(-5.6,7.2) E22(-5.6,8) E23(-5.6,8.8) F1(-4.8,-8.8) F2(-4.8,-8) F3(-4.8,-7.2) F4(-4.8,-6.4) F5(-4.8,-5.6) F19(-4.8,5.6) F20(-4.8,6.4) F21(-4.8,7.2) F22(-4.8,8) F23(-4.8,8.8) G1(-4,-8.8) G2(-4,-8) G3(-4,-7.2) G4(-4,-6.4) G5(-4,-5.6) G7(-4,-4) G8(-4,-3.2) G9(-4,-2.4) G10(-4,-1.6) G11(-4,-0.8) G12(-4,0) G13(-4,0.8) G14(-4,1.6) G15(-4,2.4) G16(-4,3.2) G17(-4,4) G19(-4,5.6) G20(-4,6.4) G21(-4,7.2) G22(-4,8) G23(-4,8.8) H1(-3.2,-8.8) H2(-3.2,-8) H3(-3.2,-7.2) H4(-3.2,-6.4) H5(-3.2,-5.6) H7(-3.2,-4) H8(-3.2,-3.2) H9(-3.2,-2.4) H10(-3.2,-1.6) H11(-3.2,-0.8) H12(-3.2,0) H13(-3.2,0.8) H14(-3.2,1.6) H15(-3.2,2.4) H16(-3.2,3.2) H17(-3.2,4) H19(-3.2,5.6) H20(-3.2,6.4) H21(-3.2,7.2) H22(-3.2,8) H23(-3.2,8.8) J1(-2.4,-8.8) J2(-2.4,-8) J3(-2.4,-7.2) J4(-2.4,-6.4) J5(-2.4,-5.6) J7(-2.4,-4) J8(-2.4,-3.2) J9(-2.4,-2.4) J10(-2.4,-1.6) J11(-2.4,-0.8) J12(-2.4,0) J13(-2.4,0.8) J14(-2.4,1.6) J15(-2.4,2.4) J16(-2.4,3.2) J17(-2.4,4) J19(-2.4,5.6) J20(-2.4,6.4) J21(-2.4,7.2) J22(-2.4,8) J23(-2.4,8.8) K1(-1.6,-8.8) K2(-1.6,-8) K3(-1.6,-7.2) K4(-1.6,-6.4) K5(-1.6,-5.6) K7(-1.6,-4) K8(-1.6,-3.2) K9(-1.6,-2.4) K10(-1.6,-1.6) K11(-1.6,-0.8) K12(-1.6,0) K13(-1.6,0.8) K14(-1.6,1.6) K15(-1.6,2.4) K16(-1.6,3.2) K17(-1.6,4) K19(-1.6,5.6) K20(-1.6,6.4) K21(-1.6,7.2) K22(-1.6,8) K23(-1.6,8.8) L1(-0.8,-8.8) L2(-0.8,-8) L3(-0.8,-7.2) L4(-0.8,-6.4) L5(-0.8,-5.6) L7(-0.8,-4) L8(-0.8,-3.2) L9(-0.8,-2.4) L10(-0.8,-1.6) L11(-0.8,-0.8) L12(-0.8,0) L13(-0.8,0.8) L14(-0.8,1.6) L15(-0.8,2.4) L16(-0.8,3.2) L17(-0.8,4) L19(-0.8,5.6) L20(-0.8,6.4) L21(-0.8,7.2) L22(-0.8,8) L23(-0.8,8.8) M1(0,-8.8) M2(0,-8) M3(0,-7.2) M4(0,-6.4) M5(0,-5.6) M7(0,-4) M8(0,-3.2) M9(0,-2.4) M10(0,-1.6) M11(0,-0.8) M12(0,0) M13(0,0.8) M14(0,1.6) M15(0,2.4) M16(0,3.2) M17(0,4) M19(0,5.6) M20(0,6.4) M21(0,7.2) M22(0,8) M23(0,8.8) N1(0.8,-8.8) N2(0.8,-8) N3(0.8,-7.2) N4(0.8,-6.4) N5(0.8,-5.6) N7(0.8,-4) N8(0.8,-3.2) N9(0.8,-2.4) N10(0.8,-1.6) N11(0.8,-0.8) N12(0.8,0) N13(0.8,0.8) N14(0.8,1.6) N15(0.8,2.4) N16(0.8,3.2) N17(0.8,4) N19(0.8,5.6) N20(0.8,6.4) N21(0.8,7.2) N22(0.8,8) N23(0.8,8.8) P1(1.6,-8.8) P2(1.6,-8) P3(1.6,-7.2) P4(1.6,-6.4) P5(1.6,-5.6) P7(1.6,-4) P8(1.6,-3.2) P9(1.6,-2.4) P10(1.6,-1.6) P11(1.6,-0.8) P12(1.6,0) P13(1.6,0.8) P14(1.6,1.6) P15(1.6,2.4) P16(1.6,3.2) P17(1.6,4) P19(1.6,5.6) P20(1.6,6.4) P21(1.6,7.2) P22(1.6,8) P23(1.6,8.8) R1(2.4,-8.8) R2(2.4,-8) R3(2.4,-7.2) R4(2.4,-6.4) R5(2.4,-5.6) R7(2.4,-4) R8(2.4,-3.2) R9(2.4,-2.4) R10(2.4,-1.6) R11(2.4,-0.8) R12(2.4,0) R13(2.4,0.8) R14(2.4,1.6) R15(2.4,2.4) R16(2.4,3.2) R17(2.4,4) R19(2.4,5.6) R20(2.4,6.4) R21(2.4,7.2) R22(2.4,8) R23(2.4,8.8) T1(3.2,-8.8) T2(3.2,-8) T3(3.2,-7.2) T4(3.2,-6.4) T5(3.2,-5.6) T7(3.2,-4) T8(3.2,-3.2) T9(3.2,-2.4) T10(3.2,-1.6) T11(3.2,-0.8) T12(3.2,0) T13(3.2,0.8) T14(3.2,1.6) T15(3.2,2.4) T16(3.2,3.2) T17(3.2,4) T19(3.2,5.6) T20(3.2,6.4) T21(3.2,7.2) T22(3.2,8) T23(3.2,8.8) U1(4,-8.8) U2(4,-8) U3(4,-7.2) U4(4,-6.4) U5(4,-5.6) U7(4,-4) U8(4,-3.2) U9(4,-2.4) U10(4,-1.6) U11(4,-0.8) U12(4,0) U13(4,0.8) U14(4,1.6) U15(4,2.4) U16(4,3.2) U17(4,4) U19(4,5.6) U20(4,6.4) U21(4,7.2) U22(4,8) U23(4,8.8) V1(4.8,-8.8) V2(4.8,-8) V3(4.8,-7.2) V4(4.8,-6.4) V5(4.8,-5.6) V19(4.8,5.6) V20(4.8,6.4) V21(4.8,7.2) V22(4.8,8) V23(4.8,8.8) W1(5.6,-8.8) W2(5.6,-8) W3(5.6,-7.2) W4(5.6,-6.4) W5(5.6,-5.6) W6(5.6,-4.8) W7(5.6,-4) W8(5.6,-3.2) W9(5.6,-2.4) W10(5.6,-1.6) W11(5.6,-0.8) W12(5.6,0) W13(5.6,0.8) W14(5.6,1.6) W15(5.6,2.4) W16(5.6,3.2) W17(5.6,4) W18(5.6,4.8) W19(5.6,5.6) W20(5.6,6.4) W21(5.6,7.2) W22(5.6,8) W23(5.6,8.8) Y1(6.4,-8.8) Y2(6.4,-8) Y3(6.4,-7.2) Y4(6.4,-6.4) Y5(6.4,-5.6) Y6(6.4,-4.8) Y7(6.4,-4) Y8(6.4,-3.2) Y9(6.4,-2.4) Y10(6.4,-1.6) Y11(6.4,-0.8) Y12(6.4,0) Y13(6.4,0.8) Y14(6.4,1.6) Y15(6.4,2.4) Y16(6.4,3.2) Y17(6.4,4) Y18(6.4,4.8) Y19(6.4,5.6) Y20(6.4,6.4) Y21(6.4,7.2) Y22(6.4,8) Y23(6.4,8.8)
A694B
  rect 1.524x1.524 hole 1.016: A1(2.54,1.27)
  round 1.524 hole 1.016: A2(0,1.27) C1(2.54,-1.27) C2(0,-1.27)
AP7365_SOT25
  rect 0.508x1.016 smd: 1(-0.95,-1.3) 2(0,-1.3) 3(0.95,-1.3) 4(0.95,1.3) 5(-0.95,1.3)
C0402
  rect 0.635x0.508 smd: 1(-0.508,0) 2(0.508,0)
C0402_BGA
  custom 0.119x0.119 smd: 1(-0.47,0) 2(0.47,0)
C0603
  rect 0.889x0.813 smd: 1(-0.762,0) 2(0.762,0)
C0805
  rect 1.143x1.27 smd: 1(-0.889,0) 2(0.889,0)
C1206
  rect 1.397x1.651 smd: 1(-1.397,0) 2(1.397,0)
CAP_D8_SMT
  rect 4.191x1.397 smd: 1(-3.3,0) 2(3.3,0)
CON4P2_54MM
  rect 1.524x1.524 hole 1.016: 1(-6.35,-0.635)
  round 1.524 hole 1.016: 2(-3.81,-0.635) 3(-1.27,-0.635) 4(1.27,-0.635)
CRY2P_5032
  rect 2.032x2.54 smd: 1(-2,0) 2(2,0)
DIP
  round 1.524 hole 1.016: 1(0,0)
FAN_CONNECTOR
  rect 2.032x2.032 hole 1.524: 1(2.54,0)
  round 2.032 hole 1.524: 2(0,0) 3(-2.54,0)
FB0603
  rect 0.762x0.813 smd: 1(-0.762,0) 2(0.762,0)
G5795F11U_SOP8FD
  rect 0.635x1.778 smd: 1(-1.905,-2.667) 2(-0.635,-2.667) 3(0.635,-2.667) 4(1.905,-2.667) 5(1.905,2.667) 6(0.635,2.667) 7(-0.635,2.667) 8(-1.905,2.667)
  rect 3.8x2.64 smd: 9(0,0)
HDR2_2_54MM_DIP
  rect 1.524x1.524 hole 1.016: 1(-1.27,0)
  round 1.524 hole 1.016: 2(1.27,0)
HDR6_2X3_2_54MM_DIP
  rect 1.524x1.524 hole 1.016: 1(-2.54,-1.27)
  round 1.524 hole 1.016: 2(-2.54,1.27) 3(0,-1.27) 4(0,1.27) 5(2.54,-1.27) 6(2.54,1.27)
HOLE3_5P-8MM
  round 5.08 hole 3.505: 1(0,0)
IHLP2525
  rect 1.829x3.429 smd: 1(-2.769,0) 2(2.769,0)
IHLP4040
  rect 3.175x4.953 smd: 1(-4.5,0) 2(4.5,0)
IHLP5050
  rect 2.946x4.953 smd: (-5.41,0) (5.41,0)
  rect 2.438x11.328 smd: 1(-3.327,0) 2(3.327,0)
JPD1030_H224_4F
  oval 1.524x3.937 hole 0.762x3.175: 1(2.45,0)
  oval 1.27x3.302 hole 0.508x2.54: 2(-3.35,0)
  oval 3.429x1.524 hole 2.667x0.762: 3(-0.65,-4.7)
LED0603
  rect 1.016x0.762 smd: 1(-0.787,0) 2(0.787,0)
MINI_USB_B
  rect 2.032x2.54 smd: (-4.45,2.325) (-4.45,-3.175) (4.45,2.325) (4.45,-3.175)
  round 0.914 hole 0.914 unplated: (-2.2,-0.225) (2.2,-0.225)
  rect 0.508x2.311 smd: 1(-1.6,2.425) 2(-0.8,2.425) 3(0,2.425) 4(0.8,2.425) 5(1.6,2.425)
OSC5032
  rect 1.905x1.27 smd: 1(-1.9,-1.15) 2(1.9,-1.15) 3(1.9,1.15) 4(-1.9,1.15)
PCIE_2X2P_RA
  rect 2.4x2.4 hole 1.8: 1(-2.1,2.75)
  round 2.4 hole 1.8: 2(2.1,2.75) 3(2.1,-2.75) 4(-2.1,-2.75)
QFN24-0-5
  oval 0.9x0.25 smd: 1(-2.01,1.2) 2(-2.01,0.7) 3(-2.01,0.2) 4(-2.01,-0.3) 5(-2.01,-0.8) 6(-2.01,-1.3) 13(2.01,-1.3) 14(2.01,-0.8) 15(2.01,-0.3) 16(2.01,0.2) 17(2.01,0.7) 18(2.01,1.2)
  oval 0.25x0.9 smd: 7(-1.25,-2) 8(-0.75,-2) 9(-0.25,-2) 10(0.25,-2) 11(0.75,-2) 12(1.25,-2) 19(1.25,2) 20(0.75,2) 21(0.25,2) 22(-0.25,2) 23(-0.75,2) 24(-1.25,2)
  rect 2.54x2.54 smd: 25(0,0)
QFN32_5X5_R5
  oval 0.889x0.279 smd: 1(-2.45,1.75) 2(-2.45,1.25) 3(-2.45,0.75) 4(-2.45,0.25) 5(-2.45,-0.25) 6(-2.45,-0.75) 7(-2.45,-1.25) 8(-2.45,-1.75) 17(2.45,-1.75) 18(2.45,-1.25) 19(2.45,-0.75) 20(2.45,-0.25) 21(2.45,0.25) 22(2.45,0.75) 23(2.45,1.25) 24(2.45,1.75)
  oval 0.279x0.889 smd: 9(-1.75,-2.45) 10(-1.25,-2.45) 11(-0.75,-2.45) 12(-0.25,-2.45) 13(0.25,-2.45) 14(0.75,-2.45) 15(1.25,-2.45) 16(1.75,-2.45) 25(1.75,2.45) 26(1.25,2.45) 27(0.75,2.45) 28(0.25,2.45) 29(-0.25,2.45) 30(-0.75,2.45) 31(-1.25,2.45) 32(-1.75,2.45)
  rect 3.277x3.277 smd: 33(0,0)
QFN40
  rect 0.813x0.229 smd: 1(-2.997,2.286) 2(-2.997,1.778) 3(-2.997,1.27) 4(-2.997,0.762) 5(-2.997,0.254) 6(-2.997,-0.254) 7(-2.997,-0.762) 8(-2.997,-1.27) 9(-2.997,-1.778) 10(-2.997,-2.286) 21(2.997,-2.286) 22(2.997,-1.778) 23(2.997,-1.27) 24(2.997,-0.762) 25(2.997,-0.254) 26(2.997,0.254) 27(2.997,0.762) 28(2.997,1.27) 29(2.997,1.778) 30(2.997,2.286)
  rect 0.229x0.813 smd: 11(-2.286,-2.997) 12(-1.778,-2.997) 13(-1.27,-2.997) 14(-0.762,-2.997) 15(-0.254,-2.997) 16(0.254,-2.997) 17(0.762,-2.997) 18(1.27,-2.997) 19(1.778,-2.997) 20(2.286,-2.997) 31(2.286,2.997) 32(1.778,2.997) 33(1.27,2.997) 34(0.762,2.997) 35(0.254,2.997) 36(-0.254,2.997) 37(-0.762,2.997) 38(-1.27,2.997) 39(-1.778,2.997) 40(-2.286,2.997)
  rect 4.369x4.369 smd: 41(0,0)
R0402
  rect 0.635x0.508 smd: 1(-0.508,0) 2(0.508,0)
R0603
  rect 0.762x0.813 smd: 1(-0.762,0) 2(0.762,0)
R0805
  rect 1.016x1.143 smd: 1(-1.016,0) 2(1.016,0)
R2512
  rect 1.524x3.175 smd: 1(-3.302,0) 2(3.302,0)
SO-8
  oval 2.032x0.61 smd: 1(-2.794,1.905) 2(-2.794,0.635) 3(-2.794,-0.635) 4(-2.794,-1.905) 5(2.794,-1.905) 6(2.794,-0.635) 7(2.794,0.635) 8(2.794,1.905)
SOD323
  rect 0.991x0.508 smd: A(-1.253,0) C(1.253,0)
SOIC8_TI
  rect 0.635x1.651 smd: 1(-1.905,-2.8) 2(-0.635,-2.8) 3(0.635,-2.8) 4(1.905,-2.8) 5(1.905,2.8) 6(0.635,2.8) 7(-0.635,2.8) 8(-1.905,2.8)
SON-5X6
  rect 1.372x0.711 smd: 1(-2.759,1.905) 2(-2.759,0.635) 3(-2.759,-0.635) 4(-2.759,-1.905) 6(1.397,1.651) 7(1.397,0.381) 8(1.397,-1.143)
  rect 4.445x4.521 smd: 5(1.249,0)
SON-8
  rect 1.499x4.699 smd: (2.3,0)
  rect 1.143x0.711 smd: 1(-3.175,1.905) 2(-3.175,0.635) 3(-3.175,-0.635) 4(-3.175,-1.905)
  rect 3.099x4.191 smd: 5(0,0)
SOP8
  oval 1.905x0.61 smd: 1(-2.87,1.905) 2(-2.87,0.635) 3(-2.87,-0.635) 4(-2.87,-1.905) 5(2.87,-1.905) 6(2.87,-0.635) 7(2.87,0.635) 8(2.87,1.905)
SOT23
  rect 1.016x1.27 smd: 1(-1.016,-1.143) 2(1.016,-1.143) 3(0,1.143)
SOT23DGS
  rect 0.914x0.864 smd: D(1.016,0) G(-1.016,0.889) S(-1.016,-0.889)
SOT143-4
  rect 1.016x1.27 smd: 1(-0.826,-1.27)
  rect 0.889x1.27 smd: 2(0.953,-1.27) 3(0.953,1.27) 4(-0.953,1.27)
SOT143-25X60
  rect 1.524x1.016 smd: 1(0.965,-0.749)
  rect 1.524x0.635 smd: 2(0.965,0.953) 3(-0.965,0.953) 4(-0.965,-0.953)
SOT-23-5
  rect 0.62x1.22 smd: 1(-0.95,-1.31) 2(0,-1.31) 3(0.95,-1.31) 4(0.95,1.31) 5(-0.95,1.31)
SOT-23_PMOS
  rect 1.016x1.397 smd: 1(-0.95,-1.1) 2(0.95,-1.1) 3(0,1.1)
SOT-223
  rect 1.524x2.032 smd: 1(-2.31,-3.15) 2(0,-3.15) 3(2.31,-3.15)
  rect 3.81x2.032 smd: 4(0,3.15)
SRPI_0604
  rect 2.54x3.556 smd: 1(-3.1,0) 2(3.1,0)
TC7343
  rect 3.302x2.413 smd: 1(-3.81,0) 2(3.81,0)
TPAD_020
  round 0.508 smd: 1(0,0)
TS039
  round 1.778 hole 1.016: 1(-2.25,-2.25) 2(2.25,-2.25)
  round 1.905 hole 1.397: 3(-3.5,0.25) 4(3.5,0.25)
TSSOP20
  rect 2.007x0.356 smd: 1(-3.76,2.925)
  oval 2.007x0.356 smd: 2(-3.76,2.275) 3(-3.76,1.625) 4(-3.76,0.975) 5(-3.76,0.325) 6(-3.76,-0.325) 7(-3.76,-0.975) 8(-3.76,-1.625) 9(-3.76,-2.275) 10(-3.76,-2.925) 11(3.76,-2.925) 12(3.76,-2.275) 13(3.76,-1.625) 14(3.76,-0.975) 15(3.76,-0.325) 16(3.76,0.325) 17(3.76,0.975) 18(3.76,1.625) 19(3.76,2.275) 20(3.76,2.925)
unnamed
  round 1.016 smd: 1(0,0)

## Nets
AGND_THS: C24.2 C382.2 FB11.1(FB1) U5.B23(AGND_THS)
AVDD_THS: C24.1 C382.1 FB4.2(FB2) U5.A22(AVDD_THS)
GND_SIGNAL: C334.1 C335.1 C336.2 C337.2 C338.2 C339.1 C340.2 C341.1 C342.2 C343.2 C344.2 C346.2 C347.2 C348.2 C349.2 C383.1 C384.1 C385.1 C386.1 D9.5(AN) ER3.1 J5.6 J6.6 J7.6 J8.6 R155.2 R157.2 R163.2 R165.2 R166.2 R167.2 R168.2
P12V_FLT: C249.2 C250.2 C252.2 C253.2 C257.1 C260.2 C261.2 C262.2 C263.2 C272.2 C273.2 C274.2 C275.2 C285.2 C288.2 C289.2 C290.2 C318.1 C319.1 C320.1 C321.2 C331.1 CP1.1 CP2.1 CP8.1 L2.1 Q4.5(DRAIN) Q5.5(DRAIN) Q8.5(DRAIN) Q9.5(DRAIN) Q12.5(DRAIN) Q13.5(DRAIN) Q16.5(DRAIN) Q17.5(DRAIN) Q20.5(DRAIN) R57.2 R62.2 R64.2 R73.2 R101.2 R104.2 R188.2 R240.2 U20.2(IN)
V6314_VCC: C357.2 R140.2 R213.1 R216.1 U13.18(VCC)
VBUS_5V: C380.2 D2.4(C3) J3.1(VBUS) R226.2
VCC_1V0: C336.1 C337.1 J6.2 J8.2 R159.1
VCC_1V8: C23.1 C26.1 C27.2 C28.2 C29.2 C30.2 C31.2 C32.2 C33.2 C45.1 C392.1 D19.C FB4.1(FB1) FB5.1(FB1) FB10.2(FB2) R25.1 R26.1 R27.1 R28.1 R29.1 R39.2 R46.1 R47.1 R174.1 R175.1 R183.2 R187.2 R232.1 R234.1 R235.1 U5.AB22(VDDE1) U5.AC23(VDDE5) U5.G23(VDDE2) U5.N23(VDDE3) U5.T23(VDDE4) U5.W23(VDDE6) U5.Y23(VDDE7) U6.2(VCCA) U7.5(VOUT)
VCC_3V3: C15.1 C22.2 C44.1 C350.1 C376.2 C377.2 R13.2 R14.2 R80.2 R81.2 R88.2 R91.2 R94.2 R97.2 R98.2 R141.1 R143.1 R150.2 R176.2 R177.2 R182.2 R221.2 R222.2 R224.2 R225.2 R228.1 R229.1 R230.1 R231.1 R248.2 U3.2(VOUT) U3.4(TAB) U6.19(VCCB) U7.1(VIN) U7.3(/SHUT) U18.4(VCC) U19.5(VIO) U19.6(VDD) U19.7(REGIN)
VCC_5V0: C13.2 C14.1 C330.1 C387.1 L8.1 Q22.2(SOURCE) R83.1 R84.2 R102.2 R105.1 R116.1 R140.1 R242.1 U3.3(VIN)
VCC_N0V5: C348.1 C349.1 J5.4 J7.4 R170.1
VCC_N1V0: C342.1 C343.1 J5.2 J7.2 R160.1
VCC_N5V0: C333.1 C339.2 C341.2 C345.2 C384.2 C386.2 D10.5(AN) U14.5(OUT) U16.4(V-) U17.4(V-)
VCC_P0V5: C346.1 C347.1 J6.4 J8.4 R169.1
VCC_P5V0: C328.1 C329.1 C334.2 C335.2 C383.2 C385.2 Q22.3(DRAIN) R161.2 U14.8(V+) U16.8(V+) U17.8(V+)
VDDA_OSC: C25.1 FB5.2(FB2) U5.G22(VDDA_OSC)
VDDA_PLL0: C34.1 C35.2 C36.2 C37.2 R234.2 U5.N20(VDDA_PLL0)
VDDA_PLL1: C40.1 C41.2 C42.2 C43.2 R235.2 U5.P20(VDDA_PLL1)
VSSA_PLL0: C34.2 C35.1 C36.1 C37.1 FB7.1(FB1) U5.N19(VSSA_PLL0)
VSSA_PLL1: C40.2 C41.1 C42.1 C43.1 FB9.1(FB1) U5.P19(VSSA_PLL1)
